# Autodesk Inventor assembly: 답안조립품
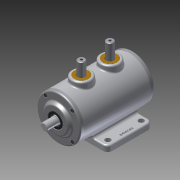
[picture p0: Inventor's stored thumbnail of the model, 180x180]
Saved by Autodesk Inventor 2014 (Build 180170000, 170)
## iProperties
Created: 2014-12
Part Number: 답안조립품
Document SubType Name: Assembly
Designer: Owner
Author: Owner
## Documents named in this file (10)
- C:\Users\Owner\Desktop\441223V1004\답안조립품.iam
- C:\Users\Owner\Desktop\441223V1004\본체.ipt
- C:\Users\Owner\Desktop\441223V1004\M4-소켓머리.ipt
- C:\Users\Owner\Desktop\441223V1004\뒷커버.ipt
- C:\Users\Owner\Desktop\441223V1004\베어링 6203.ipt
- C:\Users\Owner\Desktop\441223V1004\부시.ipt
- C:\Users\Owner\Desktop\441223V1004\슬라이더.ipt
- C:\Users\Owner\Desktop\441223V1004\앞커버.ipt
- C:\Users\Owner\Desktop\441223V1004\오일실.ipt
- C:\Users\Owner\Desktop\441223V1004\축.ipt
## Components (11 placed, 3 different names)
1. 7-베어링 6203:1
2. 8-오일실:1
3. 7-베어링 6203:2
4. 9-M4-소켓머리:1
5. 9-M4-소켓머리:3
6. 9-M4-소켓머리:4
7. 9-M4-소켓머리:5
8. 9-M4-소켓머리:2
9. 9-M4-소켓머리:6
10. 9-M4-소켓머리:7
11. 9-M4-소켓머리:8
